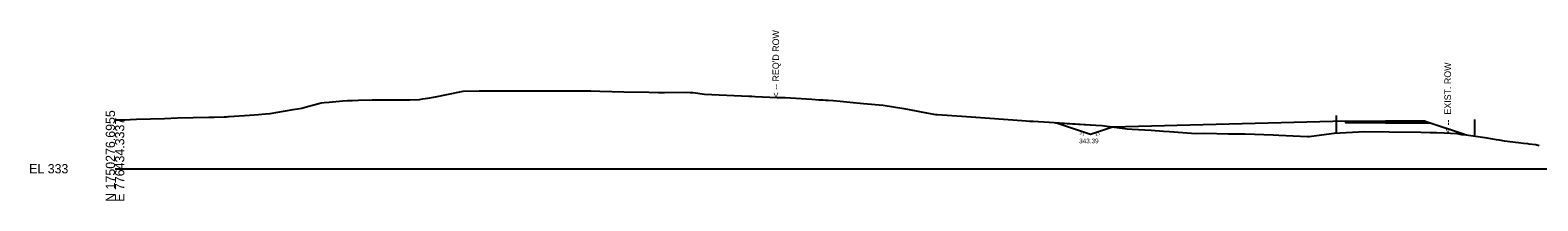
# Model space of a CAD drawing. Extents: x 776426 to 854588, y 1736205 to 1756790.
# Drawn here: x 804645.1 to 805101.4, y 1748705.1 to 1748756.6 of the extents above; entities that cross this region are included whole.
import ezdxf

# ---------------------------------------------------------------- set-up
doc = ezdxf.new("R2010")
doc.units = 0
for name, color, linetype in [('DTM CONTOURS_MAJOR_TX', 7, 'Continuous'), ('DTM_X_FLOW_ARROWS', 7, 'Continuous'), ('X_TRANS_EOP', 7, 'Continuous'), ('XS_M_SHAPES_EARTHWORK', 7, 'Continuous'), ('XS_P_DR_GRAVEL', 7, 'Continuous'), ('XS_P_FINISHED_GRADE', 7, 'Continuous'), ('XS_P_GROUND', 7, 'Continuous'), ('XS_P_ROW', 7, 'Continuous'), ('XS_P_TX_DCH', 7, 'Continuous'), ('XS_P_TX_FS_BS', 7, 'Continuous'), ('XS_X_ROW', 7, 'Continuous')]:
    doc.layers.add(name, color=color, linetype=linetype)

msp = doc.modelspace()

# ---------------------------------------------------------------- linework, layer by layer
at = {"layer": 'DTM CONTOURS_MAJOR_TX'}
msp.add_line((804670.79, 1748714.76), (805170.79, 1748714.76), dxfattribs=at)
at = {"layer": 'DTM_X_FLOW_ARROWS'}
msp.add_lwpolyline([(804670.79, 1748729.5), (804671.17, 1748729.5), (804673.84, 1748729.52), (804675.32, 1748729.6), (804677.27, 1748729.75), (804685.72, 1748729.96), (804689.66, 1748730.11), (804694.4, 1748730.22), (804699.14, 1748730.3), (804700.78, 1748730.35), (804703.78, 1748730.43), (804704.56, 1748730.46), (804704.99, 1748730.5), (804705.37, 1748730.53), (804711.51, 1748730.98), (804714.24, 1748731.17), (804716.37, 1748731.35), (804717.79, 1748731.44), (804724.74, 1748732.66), (804727.3, 1748733.11), (804728.37, 1748733.42), (804733.17, 1748734.68), (804734.12, 1748734.79), (804735.62, 1748734.92), (804739.78, 1748735.25), (804741.16, 1748735.36), (804742.71, 1748735.39), (804744.49, 1748735.5), (804748.57, 1748735.55), (804757.89, 1748735.58), (804760.06, 1748735.61), (804762.92, 1748735.72), (804763.87, 1748735.85), (804765.44, 1748736.11), (804767.76, 1748736.54), (804771.21, 1748737.19), (804776.12, 1748738.24), (804781.03, 1748738.27), (804802.04, 1748738.28), (804804.75, 1748738.34), (804812.04, 1748738.29), (804813.68, 1748738.31), (804814.83, 1748738.29), (804817.49, 1748738.22), (804824.76, 1748738.01), (804832.37, 1748737.93), (804835.28, 1748737.85), (804837.1, 1748737.85), (804843.66, 1748737.88), (804844.89, 1748737.81), (804845.74, 1748737.79), (804849.23, 1748737.34), (804862.65, 1748736.69), (804863.49, 1748736.65), (804864.57, 1748736.63), (804871.19, 1748736.28), (804873.67, 1748736.27), (804881.68, 1748735.76), (804883.78, 1748735.57), (804885.08, 1748735.54), (804885.8, 1748735.52), (804886.65, 1748735.48), (804888.19, 1748735.36), (804890.26, 1748735.19), (804893.19, 1748734.86), (804897.31, 1748734.46), (804903.33, 1748733.94), (804909.59, 1748733), (804913.26, 1748732.31), (804914.75, 1748731.98), (804919.09, 1748731.18), (804919.66, 1748731.14), (804927.07, 1748730.63), (804932.76, 1748730.26), (804942.57, 1748729.52), (804946.59, 1748729.23), (804947.61, 1748729.16), (804948.66, 1748729.1), (804951.89, 1748728.9), (804967.66, 1748727.92), (804969.59, 1748727.79), (804970.3, 1748727.7), (804973.33, 1748727.29), (804977.16, 1748726.82), (804978.62, 1748726.74), (804984.36, 1748726.38), (804988.1, 1748726.16), (804990, 1748726.05), (804997.96, 1748725.43), (805000.65, 1748725.51), (805007.86, 1748725.31), (805012.87, 1748725.31), (805021.31, 1748725.05), (805023.06, 1748724.91), (805031.69, 1748724.47), (805032.26, 1748724.55), (805039, 1748725.44), (805039.8, 1748725.55), (805049.01, 1748726.04), (805056.42, 1748725.94), (805066.07, 1748725.85), (805068.89, 1748725.75), (805070.78, 1748725.76), (805073.11, 1748725.63), (805076.95, 1748725.37), (805078.3, 1748725.15), (805078.69, 1748725.13), (805079.05, 1748725.09), (805080.42, 1748724.92), (805085.4, 1748724.24), (805087.76, 1748723.81), (805088.81, 1748723.64), (805089.78, 1748723.51), (805091.27, 1748723.16), (805095.57, 1748722.67), (805097.09, 1748722.51), (805098.34, 1748722.38), (805098.7, 1748722.32), (805100.8, 1748722.06), (805101.88, 1748721.79)], dxfattribs=at)
at = {"layer": 'X_TRANS_EOP'}
for p, q in [((805040.4, 1748730.89), (805040.4, 1748725.89)), ((805040.4, 1748730.58), (805040.4, 1748725.58)), ((805082.26, 1748729.67), (805082.26, 1748724.67)), ((805082.26, 1748729.46), (805082.26, 1748724.46))]:
    msp.add_line(p, q, dxfattribs=at)
at = {"layer": 'XS_M_SHAPES_EARTHWORK'}
msp.add_lwpolyline([(804972.73, 1748727.37), (804966.07, 1748725.15), (804955.5, 1748728.67), (804967.66, 1748727.92), (804969.59, 1748727.79), (804970.3, 1748727.7)], close=True, dxfattribs=at)
at = {"layer": 'XS_P_DR_GRAVEL'}
for points in [[(805055.32, 1748729.15), (805055.32, 1748728.65), (805043.31, 1748728.65), (805043.31, 1748729.15), (805055.32, 1748729.15)], [(805055.32, 1748729.15), (805055.32, 1748728.65), (805067.32, 1748728.65), (805067.32, 1748729.15), (805055.32, 1748729.15)], [(805067.32, 1748728.65), (805069.03, 1748728.59)]]:
    msp.add_lwpolyline(points, dxfattribs=at)
at = {"layer": 'XS_P_FINISHED_GRADE'}
for p, q in [((804966.07, 1748725.15), (804955.5, 1748728.67)), ((804972.73, 1748727.37), (804966.07, 1748725.15))]:
    msp.add_line(p, q, dxfattribs=at)
at = {"layer": 'XS_P_GROUND'}
for points in [[(805043.31, 1748729.15), (804972.73, 1748727.37)], [(805067.32, 1748729.15), (805079.81, 1748724.99)]]:
    msp.add_lwpolyline(points, dxfattribs=at)

# ---------------------------------------------------------------- texts
at = {"layer": 'DTM CONTOURS_MAJOR_TX'}
for s, p in [('N 1750276.6955', (804670.79, 1748704.76)), ('E 776434.3337', (804673.59, 1748704.76))]:
    msp.add_text(s, height=2.8, rotation=90, dxfattribs=at).set_placement(p)
msp.add_text('EL 333', height=2.8, dxfattribs=at).set_placement((804644.79, 1748713.36))
at = {"layer": 'XS_P_ROW'}
msp.add_text("< -- REQ'D ROW", height=2, rotation=90, dxfattribs=at).set_placement((804871.79, 1748736.3))
at = {"layer": 'XS_P_TX_DCH'}
msp.add_text('343.39', height=1.4, dxfattribs=at).set_placement((804962.6, 1748722.45))
at = {"layer": 'XS_P_TX_FS_BS'}
for rotation, p in [(341.5651, (804962.68, 1748725.21)), (18.4349, (804967.59, 1748724.56))]:
    msp.add_text('3:1', height=0.8, rotation=rotation, dxfattribs=at).set_placement(p)
at = {"layer": 'XS_X_ROW'}
msp.add_text('< --  EXIST. ROW', height=2, rotation=90, dxfattribs=at).set_placement((805075.17, 1748725.56))

doc.saveas('drawing.dxf')
